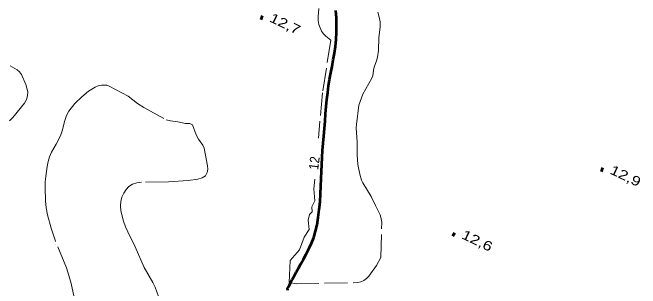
# Model space of a CAD drawing. Extents: x 355726 to 357533, y 5103782 to 5105258.
# Drawn here: x 356144.1 to 356243.2, y 5104405.7 to 5104449.2 of the extents above; entities that cross this region are included whole.
import ezdxf
from ezdxf.enums import TextEntityAlignment as Align

# ---------------------------------------------------------------- set-up
doc = ezdxf.new("R2010")
doc.units = 0
doc.header["$LTSCALE"] = 0.6
doc.linetypes.add('DASH_DOUBLE_DOT', pattern=[9.2, 5, -1.2, 0.3, -1.2, 0.3, -1.2])
doc.linetypes.add('LONG_DASHED', pattern=[7.5, 6, -1.5])
for name, color, linetype, lineweight in [('2', 7, 'LONG_DASHED', 13), ('3', 7, 'Continuous', 140), ('4', 7, 'DASH_DOUBLE_DOT', 53)]:
    doc.layers.add(name, color=color, linetype=linetype, lineweight=lineweight)

msp = doc.modelspace()

# ---------------------------------------------------------------- linework, layer by layer
at = {"layer": '2'}
for points in [[(356192.44, 5104449.86), (356192.36, 5104448.55), (356192.37, 5104447.93), (356192.45, 5104447.34), (356192.64, 5104446.79), (356192.89, 5104446.26), (356193.19, 5104445.86), (356193.55, 5104445.49), (356194.37, 5104444.86), (356193.02, 5104436.55), (356192.38, 5104429.42)], [(356191.8, 5104422.93), (356191.66, 5104421.4), (356191.83, 5104419.54), (356191.37, 5104418.57), (356191.4, 5104417.76), (356191, 5104417.36), (356190.79, 5104416.48), (356190.93, 5104415.01), (356190.14, 5104413.8), (356189.39, 5104411.8), (356187.95, 5104410.11), (356187.77, 5104406.63), (356188.86, 5104406.41), (356198.6, 5104406.63), (356199.08, 5104406.75), (356199.56, 5104406.94), (356200, 5104407.25), (356200.36, 5104407.62), (356201.56, 5104409.32), (356202.25, 5104410.59), (356202.37, 5104416.18), (356202.24, 5104416.92), (356202.12, 5104417.29), (356201.37, 5104418.76), (356200.73, 5104420.19), (356199.4, 5104422.34), (356199.2, 5104422.78), (356198.9, 5104423.7), (356198.61, 5104425.23), (356198.48, 5104426.76), (356198.5, 5104428.76), (356198.36, 5104431.04), (356198.38, 5104431.54), (356198.76, 5104434.63), (356199.39, 5104436.34), (356200.81, 5104438.88), (356200.96, 5104439.23), (356201.08, 5104440.11), (356201.2, 5104440.61), (356201.56, 5104441.59), (356201.7, 5104442.16), (356201.86, 5104443.23), (356201.94, 5104445.3), (356202.15, 5104446.92), (356202.12, 5104447.74), (356201.97, 5104448.47), (356201.76, 5104449.28)], [(356143.64, 5104432.12), (356144.18, 5104432.66), (356146.01, 5104434.92), (356146.33, 5104435.51), (356146.5, 5104436.09), (356146.52, 5104436.69), (356146.24, 5104437.86), (356145.51, 5104439.42), (356145.22, 5104439.84), (356144.86, 5104440.19), (356143.74, 5104440.83)], [(356153.99, 5104403.58), (356153.29, 5104406.7), (356152.62, 5104408.95), (356150.88, 5104413.17), (356150.21, 5104415.21), (356149.62, 5104417.3), (356149.42, 5104418.42), (356149.33, 5104419.51), (356149.26, 5104421.59), (356149.29, 5104422.5), (356149.35, 5104423.34), (356149.56, 5104424.94), (356149.72, 5104425.72), (356149.95, 5104426.46), (356150.24, 5104427.17), (356150.98, 5104428.45), (356151.68, 5104429.79), (356151.94, 5104430.54), (356152.36, 5104432.18), (356152.64, 5104432.96), (356153.02, 5104433.68), (356153.97, 5104434.87), (356155.04, 5104435.92), (356156.13, 5104436.83), (356157.14, 5104437.46), (356157.63, 5104437.63), (356158.13, 5104437.74)], [(356158.13, 5104437.74), (356159.02, 5104437.74), (356159.39, 5104437.62), (356162.36, 5104436), (356163.83, 5104434.86), (356164.81, 5104434.23), (356168.34, 5104432.3), (356169.04, 5104432.11), (356170.2, 5104431.99), (356171.39, 5104431.73), (356172.12, 5104431.7), (356172.51, 5104431.49), (356173.09, 5104429.91), (356173.48, 5104429.25), (356174.13, 5104428.32), (356174.37, 5104427.8), (356174.88, 5104425.05), (356174.92, 5104424.5), (356174.85, 5104423.96), (356174.56, 5104423.46), (356174.04, 5104423.12), (356173.34, 5104422.91), (356171.82, 5104422.7), (356168.72, 5104422.51), (356164.49, 5104422.44), (356163.72, 5104422.34), (356163.04, 5104422.13), (356162.49, 5104421.78), (356162.04, 5104421.3), (356161.66, 5104420.75), (356161.38, 5104420.11), (356161.19, 5104419.43), (356161.13, 5104418.72), (356161.23, 5104417.96), (356161.63, 5104416.29), (356161.93, 5104415.44), (356162.3, 5104414.62), (356163.48, 5104412.29), (356164.91, 5104409), (356166.27, 5104406.65), (356166.63, 5104405.88), (356167.41, 5104403.7)]]:
    msp.add_lwpolyline(points, dxfattribs=at)
at = {"layer": '3'}
for p, q in [((356183.23, 5104448.49), (356183.59, 5104448.32)), ((356236.95, 5104424.52), (356237.31, 5104424.35)), ((356213.55, 5104414.29), (356213.91, 5104414.12))]:
    msp.add_line(p, q, dxfattribs=at)
at = {"layer": '4'}
for points in [[(356192.91, 5104425.26), (356193.04, 5104427.44), (356193.13, 5104428.59), (356193.26, 5104429.73), (356193.35, 5104430.91), (356193.43, 5104432.09), (356193.52, 5104433.26), (356193.6, 5104434.38), (356193.71, 5104435.51), (356193.85, 5104436.59), (356193.99, 5104437.63), (356194.14, 5104438.67), (356194.32, 5104439.69), (356194.53, 5104440.71), (356194.73, 5104441.75), (356194.92, 5104442.8), (356195.06, 5104443.88), (356195.17, 5104444.98), (356195.22, 5104446.11), (356195.23, 5104447.24), (356195.22, 5104448.38), (356195.13, 5104449.54)], [(356187.56, 5104405.38), (356187.53, 5104405.75), (356187.67, 5104405.98), (356187.8, 5104406.22), (356188, 5104406.58), (356188.27, 5104407.09), (356188.57, 5104407.65), (356188.9, 5104408.25), (356189.25, 5104408.91), (356189.62, 5104409.59), (356190.02, 5104410.34), (356190.45, 5104411.13), (356190.9, 5104411.97), (356191.3, 5104412.82), (356191.65, 5104413.74), (356191.93, 5104414.72), (356192.17, 5104415.76), (356192.37, 5104416.91), (356192.53, 5104418.13), (356192.65, 5104419.38), (356192.72, 5104420.61), (356192.76, 5104421.83), (356192.8, 5104423), (356192.87, 5104424.13), (356192.91, 5104425.26)]]:
    msp.add_lwpolyline(points, dxfattribs=at)

# ---------------------------------------------------------------- texts
at = {"layer": '2', "width": 0.95}
msp.add_text('12', height=1.5, rotation=82.864, dxfattribs=at).set_placement((356192.472, 5104425.377), align=Align.CENTER)
at = {"layer": '3', "width": 1.3}
for s, p in [('12,7   ', (356184.52, 5104447.86)), ('12,9   ', (356238.24, 5104423.88)), ('12,6   ', (356214.84, 5104413.66))]:
    msp.add_text(s, height=1.5, rotation=334.423, dxfattribs=at).set_placement(p)

doc.saveas('drawing.dxf')
